// Mitsubishi GX Works2 project: 扫码程序   PLC: FX3U/FX3UC

PROGRAM MAIN
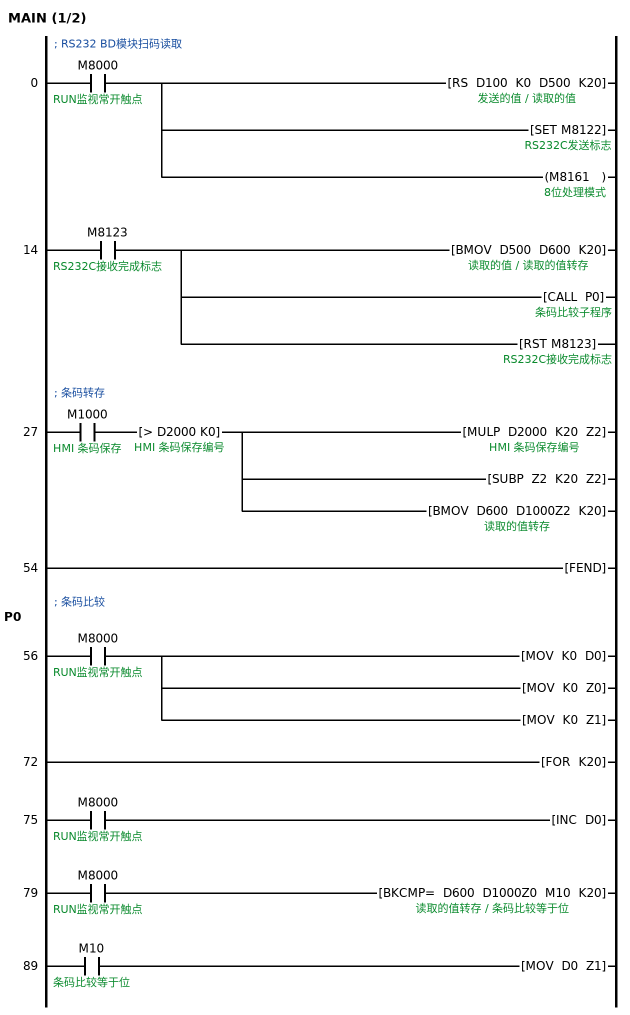
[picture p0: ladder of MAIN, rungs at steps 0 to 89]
; RS232 BD模块扫码读取
0     LD      M8000  ; RUN监视常开触点
      RS      D100 K0 D500 K20  ; 发送的值 / 读取的值
      SET     M8122  ; RS232C发送标志
      OUT     M8161  ; 8位处理模式
14    LD      M8123  ; RS232C接收完成标志
      BMOV    D500 D600 K20  ; 读取的值转存
      CALL    P0  ; 条码比较子程序
      RST     M8123  ; RS232C接收完成标志
; 条码转存
; 
27    LD      M1000  ; HMI 条码保存
      AND>    D2000 K0  ; HMI 条码保存编号
      MULP    D2000 K20 Z2
      SUBP    Z2 K20 Z2
      BMOV    D600 D1000Z2 K20
54    FEND
      P0
; 条码比较
56    LD      M8000  ; RUN监视常开触点
      MOV     K0 D0
      MOV     K0 Z0
      MOV     K0 Z1
72    FOR     K20
75    LD      M8000  ; RUN监视常开触点
      INC     D0
79    LD      M8000  ; RUN监视常开触点
      BKCMP=  D600 D1000Z0 M10 K20  ; 条码比较等于位
89    LD      M10  ; 条码比较等于位
      MOV     D0 Z1
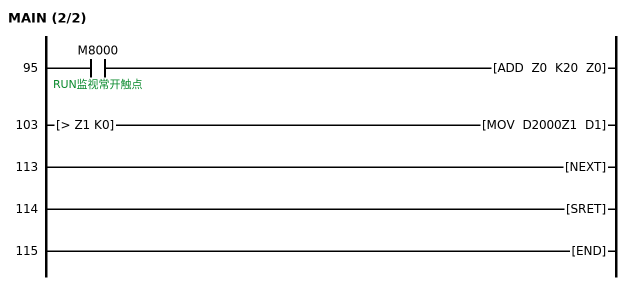
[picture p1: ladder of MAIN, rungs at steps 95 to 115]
95    LD      M8000  ; RUN监视常开触点
      ADD     Z0 K20 Z0
103   LD>     Z1 K0
      MOV     D2000Z1 D1
113   NEXT
114   SRET
115   END
END_PROGRAM

// device comments not shown above
M0  ; 触发扫码
D980  ; 条码储存始地址
D1000  ; 条码转存首地址
D1020  ; 条码1
D1040  ; 条码2
D1060  ; 条码3
D1080  ; 条码4
D1100  ; 条码5
D1120  ; 条码6
D1140  ; 条码7
D1160  ; 条码8
D1180  ; 条码9
D1200  ; 条码10
D1220  ; 条码11
D1240  ; 条码12
D1260  ; 条码13
D1280  ; 条码14
D1300  ; 条码15
D1320  ; 条码16
D1340  ; 条码17
D1360  ; 条码18
D1380  ; 条码19
D1400  ; 条码20
